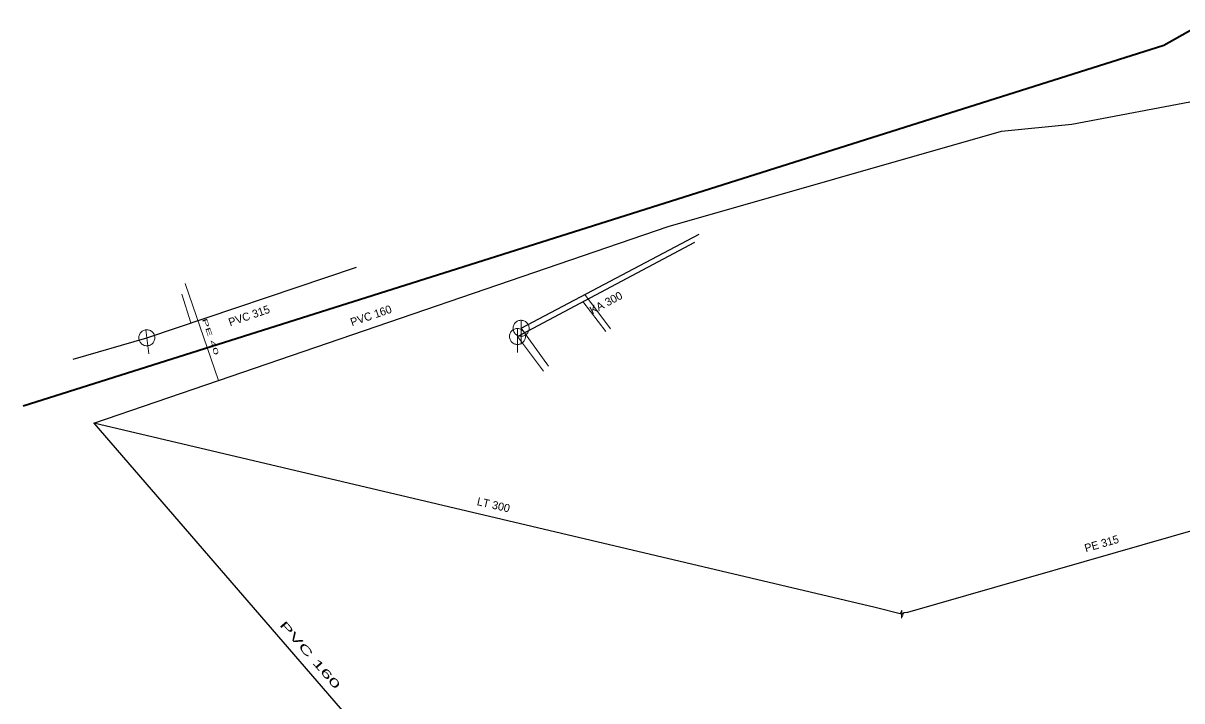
# Model space of a CAD drawing. Extents: x -809028 to -807737, y -990545 to -989489.
# Drawn here: x -808880.6 to -808735.9, y -989734.7 to -989650 of the extents above; entities that cross this region are included whole.
import ezdxf

# ---------------------------------------------------------------- set-up
doc = ezdxf.new("R2010")
doc.units = 0
doc.header["$LTSCALE"] = 0.32
for name, color, linetype, lineweight in [('1', 7, 'Continuous', 13), ('11', 7, 'Continuous', 13), ('13', 7, 'Continuous', 13), ('14', 7, 'Continuous', 25), ('17', 7, 'Continuous', 25), ('22', 7, 'Continuous', 13), ('47', 7, 'Continuous', 13)]:
    doc.layers.add(name, color=color, linetype=linetype, lineweight=lineweight)

msp = doc.modelspace()

# ---------------------------------------------------------------- linework, layer by layer
at = {"layer": '11'}
for p, q in [((-808860.837, -989683.91), (-808859.687, -989687.478)), ((-808807.851, -989688.56), (-808810.726, -989684.822)), ((-808807.274, -989688.214), (-808810.479, -989683.944)), ((-808815.011, -989692.89), (-808818.441, -989688.148)), ((-808815.646, -989693.526), (-808818.895, -989689.176))]:
    msp.add_line(p, q, dxfattribs=at)
at = {"layer": '13'}
msp.add_line((-808860.398, -989682.559), (-808856.256, -989694.666), dxfattribs=at)
at = {"layer": '14'}
for p, q in [((-808818.441, -989688.148), (-808796.206, -989676.408)), ((-808818.895, -989689.176), (-808796.755, -989677.377))]:
    msp.add_line(p, q, dxfattribs=at)
msp.add_lwpolyline([(-808874.406, -989692.006), (-808865.199, -989689.34), (-808839.018, -989680.497)], dxfattribs=at)
at = {"layer": '17', "lineweight": 35}
msp.add_lwpolyline([(-808390.05, -989488.82), (-808497.072, -989504.425), (-808538.499, -989529.548), (-808604.456, -989572.659), (-808615.372, -989579.824), (-808644.219, -989598.517), (-808658.55, -989607.941), (-808738.156, -989652.818), (-808880.644, -989697.874)], dxfattribs=at)
at = {"layer": '17'}
for points in [[(-808749.655, -989662.66), (-808733.379, -989659.583), (-808721.776, -989657.149), (-808692.364, -989669.05), (-808689.256, -989675.329), (-808683.992, -989687.256)], [(-808871.8, -989699.989), (-808856.256, -989694.666), (-808800.068, -989675.421), (-808758.445, -989663.532), (-808749.655, -989662.66)], [(-808770.905, -989723.872), (-808774.202, -989723.033), (-808871.8, -989699.989)], [(-808871.8, -989699.989), (-808822.493, -989757.074), (-808796.601, -989770.381), (-808784.798, -989773.302)], [(-808770.905, -989723.872), (-808770.592, -989723.635), (-808770.149, -989723.594), (-808733.61, -989713.1), (-808718.888, -989708.872), (-808717.285, -989708.465), (-808716.958, -989708.447)]]:
    msp.add_lwpolyline(points, dxfattribs=at)
at = {"layer": '22'}
for p, q in [((-808818.895, -989691.176), (-808818.894, -989688.176)), ((-808818.441, -989690.148), (-808818.44, -989687.148)), ((-808864.96, -989691.326), (-808865.318, -989688.347))]:
    msp.add_line(p, q, dxfattribs=at)
for points in [[(-808817.895, -989689.176), (-808817.9, -989689.067), (-808817.918, -989688.959), (-808817.948, -989688.853), (-808817.988, -989688.752), (-808818.04, -989688.655), (-808818.102, -989688.565), (-808818.174, -989688.482), (-808818.254, -989688.408), (-808818.342, -989688.342), (-808818.436, -989688.287), (-808818.536, -989688.242), (-808818.641, -989688.209), (-808818.748, -989688.187), (-808818.857, -989688.177), (-808818.967, -989688.179), (-808819.075, -989688.193), (-808819.182, -989688.218), (-808819.285, -989688.255), (-808819.383, -989688.304), (-808819.475, -989688.362), (-808819.561, -989688.431), (-808819.638, -989688.508), (-808819.707, -989688.594), (-808819.766, -989688.686), (-808819.814, -989688.784), (-808819.851, -989688.887), (-808819.877, -989688.994), (-808819.891, -989689.102), (-808819.894, -989689.212), (-808819.884, -989689.321), (-808819.863, -989689.428), (-808819.829, -989689.532), (-808819.785, -989689.632), (-808819.73, -989689.727), (-808819.664, -989689.815), (-808819.59, -989689.895), (-808819.507, -989689.967), (-808819.417, -989690.029), (-808819.321, -989690.081), (-808819.219, -989690.122), (-808819.114, -989690.152), (-808819.006, -989690.17), (-808818.896, -989690.176), (-808818.787, -989690.17), (-808818.679, -989690.152), (-808818.574, -989690.123), (-808818.472, -989690.082), (-808818.375, -989690.03), (-808818.285, -989689.968), (-808818.202, -989689.897), (-808818.127, -989689.817), (-808818.062, -989689.729), (-808818.006, -989689.635), (-808817.962, -989689.535), (-808817.928, -989689.431), (-808817.906, -989689.323), (-808817.896, -989689.214)], [(-808817.441, -989688.148), (-808817.446, -989688.039), (-808817.464, -989687.931), (-808817.494, -989687.825), (-808817.534, -989687.724), (-808817.586, -989687.627), (-808817.648, -989687.537), (-808817.72, -989687.454), (-808817.8, -989687.38), (-808817.888, -989687.314), (-808817.982, -989687.259), (-808818.082, -989687.214), (-808818.187, -989687.181), (-808818.294, -989687.159), (-808818.403, -989687.149), (-808818.513, -989687.151), (-808818.621, -989687.165), (-808818.728, -989687.19), (-808818.831, -989687.227), (-808818.929, -989687.276), (-808819.021, -989687.334), (-808819.107, -989687.403), (-808819.184, -989687.48), (-808819.253, -989687.566), (-808819.312, -989687.658), (-808819.36, -989687.756), (-808819.397, -989687.859), (-808819.423, -989687.966), (-808819.437, -989688.074), (-808819.44, -989688.184), (-808819.43, -989688.293), (-808819.409, -989688.4), (-808819.375, -989688.504), (-808819.331, -989688.604), (-808819.276, -989688.699), (-808819.21, -989688.787), (-808819.136, -989688.867), (-808819.053, -989688.939), (-808818.963, -989689.001), (-808818.867, -989689.053), (-808818.765, -989689.094), (-808818.66, -989689.124), (-808818.552, -989689.142), (-808818.442, -989689.148), (-808818.333, -989689.142), (-808818.225, -989689.124), (-808818.12, -989689.095), (-808818.018, -989689.054), (-808817.921, -989689.002), (-808817.831, -989688.94), (-808817.748, -989688.869), (-808817.673, -989688.789), (-808817.608, -989688.701), (-808817.552, -989688.607), (-808817.508, -989688.507), (-808817.474, -989688.403), (-808817.452, -989688.295), (-808817.442, -989688.186)], [(-808864.206, -989689.221), (-808864.225, -989689.113), (-808864.255, -989689.008), (-808864.298, -989688.907), (-808864.349, -989688.811), (-808864.413, -989688.721), (-808864.485, -989688.639), (-808864.566, -989688.565), (-808864.655, -989688.501), (-808864.75, -989688.446), (-808864.85, -989688.403), (-808864.954, -989688.37), (-808865.062, -989688.35), (-808865.171, -989688.341), (-808865.281, -989688.344), (-808865.39, -989688.359), (-808865.495, -989688.386), (-808865.599, -989688.423), (-808865.696, -989688.472), (-808865.788, -989688.532), (-808865.872, -989688.601), (-808865.949, -989688.68), (-808866.017, -989688.765), (-808866.075, -989688.859), (-808866.123, -989688.957), (-808866.159, -989689.06), (-808866.183, -989689.167), (-808866.196, -989689.276), (-808866.197, -989689.385), (-808866.186, -989689.495), (-808866.163, -989689.602), (-808866.13, -989689.706), (-808866.083, -989689.805), (-808866.028, -989689.899), (-808865.962, -989689.987), (-808865.886, -989690.066), (-808865.803, -989690.137), (-808865.712, -989690.198), (-808865.615, -989690.249), (-808865.514, -989690.289), (-808865.407, -989690.318), (-808865.3, -989690.335), (-808865.19, -989690.34), (-808865.08, -989690.333), (-808864.973, -989690.314), (-808864.868, -989690.283), (-808864.767, -989690.242), (-808864.671, -989690.189), (-808864.58, -989690.126), (-808864.498, -989690.054), (-808864.424, -989689.973), (-808864.36, -989689.885), (-808864.305, -989689.79), (-808864.261, -989689.69), (-808864.229, -989689.585), (-808864.208, -989689.478), (-808864.199, -989689.368), (-808864.202, -989689.259)]]:
    msp.add_lwpolyline(points, close=True, dxfattribs=at)
at = {"layer": '47'}
msp.add_line((-808770.876, -989723.363), (-808771.099, -989723.822), dxfattribs=at)
msp.add_lwpolyline([(-808770.876, -989723.363), (-808770.933, -989724.38), (-808770.71, -989723.921)], dxfattribs=at)

# ---------------------------------------------------------------- texts
at = {"layer": '1'}
for s, rotation, p in [('KA 300', 28, (-808809.539, -989686.439)), ('PVC 315 ', 19, (-808854.788, -989687.918)), ('PVC 160 ', 19, (-808839.564, -989687.907)), ('LT 300', 347, (-808824.031, -989710.224)), ('PE 315', 16, (-808747.895, -989716.129))]:
    msp.add_text(s, height=1, rotation=rotation, dxfattribs=at).set_placement(p)
for s, height, rotation, width, p in [('PE 40 ', 0.6, 289, 2.2, (-808858.3, -989687.017)), ('PVC 160 ', 1, 311, 2, (-808848.689, -989725.239))]:
    msp.add_text(s, height=height, rotation=rotation, dxfattribs=dict(at, width=width)).set_placement(p)

doc.saveas('drawing.dxf')
